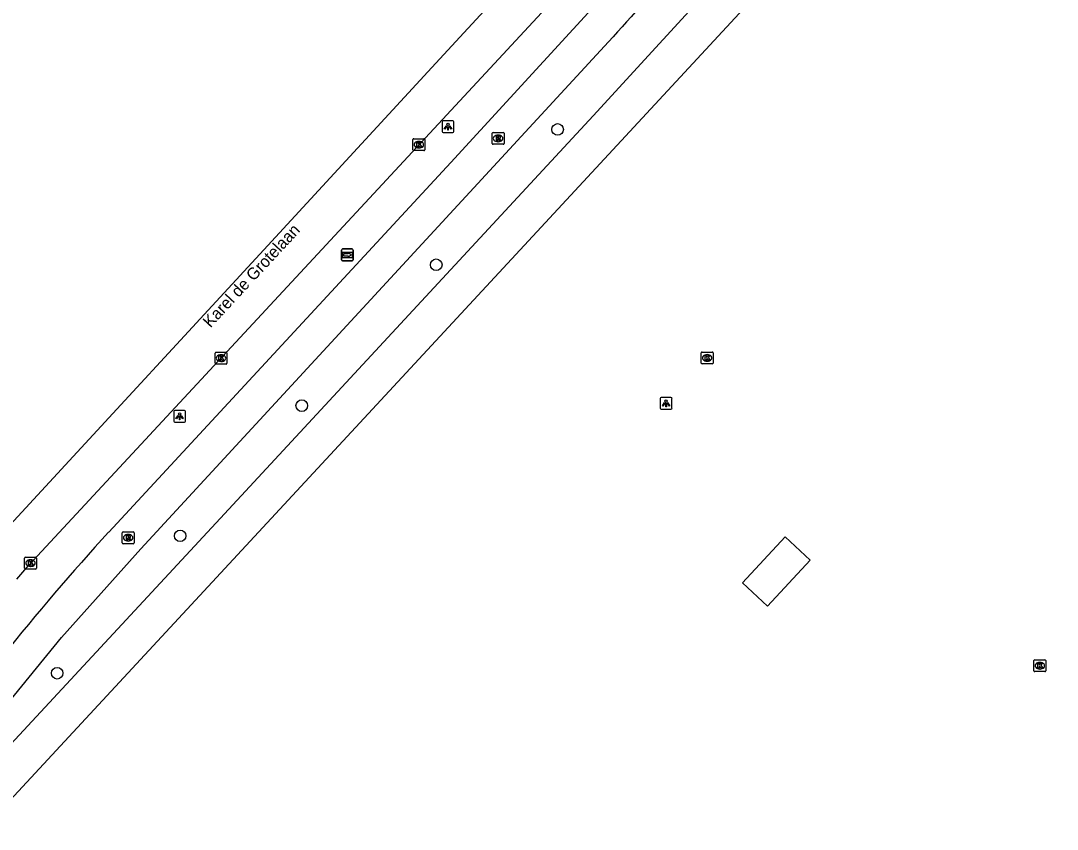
# Model space of a CAD drawing. Extents: x 159222 to 160346, y 381249 to 382166.
# Drawn here: x 159951.7 to 160039.1, y 381973.4 to 382041.6 of the extents above; entities that cross this region are included whole.
import ezdxf

# ---------------------------------------------------------------- set-up
doc = ezdxf.new("R2010")
doc.units = 0
for name, color, linetype in [('IMGEO_Boom', 7, 'Continuous'), ('IMGEO_Fietspad_gesloten', 7, 'Continuous'), ('IMGEO_Kolk', 7, 'Continuous'), ('IMGEO_Lichtpunt', 7, 'Continuous'), ('IMGEO_Openbare_ruimte_label', 7, 'Continuous'), ('IMGEO_Pand', 7, 'Continuous'), ('IMGEO_Rijbaan_regionaal_gesloten', 7, 'Continuous'), ('IMGEO_Rioolput', 7, 'Continuous'), ('IMGEO_Voetpad_open', 7, 'Continuous'), ('IMGEO_Wegwijzer', 7, 'Continuous')]:
    doc.layers.add(name, color=color, linetype=linetype)

msp = doc.modelspace()

# ---------------------------------------------------------------- linework, layer by layer
at = {"layer": 'IMGEO_Boom'}
for centre in [(159996.995, 382032.391), (159986.761, 382020.982), (159975.43, 382009.107), (159965.18, 381998.134), (159954.81, 381986.553)]:
    msp.add_circle(centre, 0.489, dxfattribs=at)
at = {"layer": 'IMGEO_Fietspad_gesloten'}
for points in [[(160000.807, 382043.591), (159987.982, 382029.591), (159959.152, 381998.446)], [(159942.998, 381974.993), (159946.971, 381979.545), (159955.163, 381989.569), (159961.853, 381997.042), (160001.291, 382039.769)]]:
    msp.add_lwpolyline(points, dxfattribs=at)
for centre, radius, start, end in [((160149.508, 381908.206), 198.185, 133.16173, 138.40657), ((160109.113, 381861.281), 203.231, 137.55179, 141.42825)]:
    msp.add_arc(centre, radius, start, end, dxfattribs=at)
at = {"layer": 'IMGEO_Kolk'}
for p, q in [((159984.799, 382030.681), (159984.799, 382031.533)), ((159984.874, 382031.607), (159985.726, 382031.607)), ((159985.8, 382031.533), (159985.8, 382030.681)), ((159985.726, 382030.607), (159984.874, 382030.607)), ((159985.31, 382030.827), (159985.285, 382030.827)), ((159985.287, 382031.387), (159985.312, 382031.387)), ((159968.121, 382012.687), (159968.121, 382013.539)), ((159968.196, 382013.613), (159969.048, 382013.613)), ((159968.609, 382013.393), (159968.634, 382013.393)), ((159969.122, 382013.539), (159969.122, 382012.687)), ((160009.098, 382012.702), (160009.098, 382013.554)), ((160009.173, 382013.628), (160010.025, 382013.628)), ((160009.586, 382013.408), (160009.611, 382013.408)), ((160010.099, 382013.554), (160010.099, 382012.702)), ((159969.048, 382012.613), (159968.196, 382012.613)), ((159968.632, 382012.833), (159968.607, 382012.833)), ((160010.025, 382012.628), (160009.173, 382012.628)), ((160009.609, 382012.848), (160009.584, 382012.848)), ((159952.063, 381995.408), (159952.063, 381996.26)), ((159952.138, 381996.334), (159952.99, 381996.334)), ((159952.551, 381996.114), (159952.576, 381996.114)), ((159953.064, 381996.26), (159953.064, 381995.408)), ((159952.99, 381995.334), (159952.138, 381995.334)), ((159952.574, 381995.554), (159952.549, 381995.554)), ((160037.144, 381986.762), (160037.144, 381987.614)), ((160037.219, 381987.688), (160038.071, 381987.688)), ((160037.655, 381986.908), (160037.63, 381986.908)), ((160037.632, 381987.468), (160037.657, 381987.468)), ((160038.145, 381987.614), (160038.145, 381986.762)), ((160038.071, 381986.688), (160037.219, 381986.688))]:
    msp.add_line(p, q, dxfattribs=at)
for points in [[(159984.799, 382030.681), (159984.799, 382031.533)], [(159984.874, 382031.607), (159985.726, 382031.607)], [(159985.8, 382031.533), (159985.8, 382030.681)], [(159985.726, 382030.607), (159984.874, 382030.607)], [(159985.12, 382031.307), (159985.243, 382031.307), (159985.243, 382031.156), (159985.373, 382031.307), (159985.537, 382031.307), (159985.391, 382031.156), (159985.544, 382030.907), (159985.392, 382030.907), (159985.307, 382031.071), (159985.243, 382031.004), (159985.243, 382030.907), (159985.12, 382030.907), (159985.12, 382031.307)], [(159968.121, 382012.687), (159968.121, 382013.539)], [(159968.196, 382013.613), (159969.048, 382013.613)], [(159968.442, 382013.313), (159968.565, 382013.313), (159968.565, 382013.162), (159968.695, 382013.313), (159968.859, 382013.313), (159968.713, 382013.162), (159968.866, 382012.913), (159968.714, 382012.913), (159968.629, 382013.077), (159968.565, 382013.01), (159968.565, 382012.913), (159968.442, 382012.913), (159968.442, 382013.313)], [(159969.122, 382013.539), (159969.122, 382012.687)], [(160009.098, 382012.702), (160009.098, 382013.554)], [(160009.173, 382013.628), (160010.025, 382013.628)], [(160009.419, 382013.328), (160009.542, 382013.328), (160009.542, 382013.177), (160009.672, 382013.328), (160009.836, 382013.328), (160009.69, 382013.177), (160009.843, 382012.928), (160009.691, 382012.928), (160009.606, 382013.092), (160009.542, 382013.025), (160009.542, 382012.928), (160009.419, 382012.928), (160009.419, 382013.328)], [(160010.099, 382013.554), (160010.099, 382012.702)], [(159969.048, 382012.613), (159968.196, 382012.613)], [(160010.025, 382012.628), (160009.173, 382012.628)], [(159952.063, 381995.408), (159952.063, 381996.26)], [(159952.138, 381996.334), (159952.99, 381996.334)], [(159952.384, 381996.034), (159952.507, 381996.034), (159952.507, 381995.883), (159952.637, 381996.034), (159952.801, 381996.034), (159952.655, 381995.883), (159952.808, 381995.634), (159952.656, 381995.634), (159952.571, 381995.798), (159952.507, 381995.731), (159952.507, 381995.634), (159952.384, 381995.634), (159952.384, 381996.034)], [(159953.064, 381996.26), (159953.064, 381995.408)], [(159952.99, 381995.334), (159952.138, 381995.334)], [(160037.144, 381986.762), (160037.144, 381987.614)], [(160037.219, 381987.688), (160038.071, 381987.688)], [(160037.465, 381987.388), (160037.588, 381987.388), (160037.588, 381987.237), (160037.718, 381987.388), (160037.882, 381987.388), (160037.736, 381987.237), (160037.889, 381986.988), (160037.737, 381986.988), (160037.652, 381987.152), (160037.588, 381987.085), (160037.588, 381986.988), (160037.465, 381986.988), (160037.465, 381987.388)], [(160038.145, 381987.614), (160038.145, 381986.762)], [(160038.071, 381986.688), (160037.219, 381986.688)]]:
    msp.add_lwpolyline(points, dxfattribs=at)
for centre, start, end in [((159984.876, 382031.531), 91.55205, 178.44795), ((159984.876, 382031.531), 91.55205, 178.44795), ((159985.724, 382031.531), 1.55205, 88.44795), ((159985.724, 382031.531), 1.55205, 88.44795), ((159984.876, 382030.683), 181.55205, 268.44795), ((159984.876, 382030.683), 181.55205, 268.44795), ((159985.724, 382030.683), 271.55205, 358.44795), ((159985.724, 382030.683), 271.55205, 358.44795), ((159968.198, 382013.537), 91.55205, 178.44795), ((159968.198, 382013.537), 91.55205, 178.44795), ((159969.046, 382013.537), 1.55205, 88.44795), ((159969.046, 382013.537), 1.55205, 88.44795), ((160009.175, 382013.552), 91.55205, 178.44795), ((160009.175, 382013.552), 91.55205, 178.44795), ((160010.023, 382013.552), 1.55205, 88.44795), ((160010.023, 382013.552), 1.55205, 88.44795), ((159968.198, 382012.689), 181.55205, 268.44795), ((159968.198, 382012.689), 181.55205, 268.44795), ((159969.046, 382012.689), 271.55205, 358.44795), ((159969.046, 382012.689), 271.55205, 358.44795), ((160009.175, 382012.704), 181.55205, 268.44795), ((160009.175, 382012.704), 181.55205, 268.44795), ((160010.023, 382012.704), 271.55205, 358.44795), ((160010.023, 382012.704), 271.55205, 358.44795), ((159952.14, 381996.258), 91.55205, 178.44795), ((159952.14, 381996.258), 91.55205, 178.44795), ((159952.988, 381996.258), 1.55205, 88.44795), ((159952.988, 381996.258), 1.55205, 88.44795), ((159952.14, 381995.41), 181.55205, 268.44795), ((159952.14, 381995.41), 181.55205, 268.44795), ((159952.988, 381995.41), 271.55205, 358.44795), ((159952.988, 381995.41), 271.55205, 358.44795), ((160037.221, 381987.612), 91.55205, 178.44795), ((160037.221, 381987.612), 91.55205, 178.44795), ((160038.069, 381987.612), 1.55205, 88.44795), ((160038.069, 381987.612), 1.55205, 88.44795), ((160037.221, 381986.764), 181.55205, 268.44795), ((160037.221, 381986.764), 181.55205, 268.44795), ((160038.069, 381986.764), 271.55205, 358.44795), ((160038.069, 381986.764), 271.55205, 358.44795)]:
    msp.add_arc(centre, 0.0765, start, end, dxfattribs=at)
for centre, major_axis, ratio, start_param, end_param in [((159985.286, 382031.107), (-0.387, 0.002), 0.722429, 4.712389, 7.853982), ((159985.311, 382031.107), (-0.39, 0.002), 0.717154, 1.570796, 4.712389), ((159968.608, 382013.113), (-0.387, 0.002), 0.722429, 4.712389, 7.853982), ((159968.633, 382013.113), (-0.39, 0.002), 0.717154, 1.570796, 4.712389), ((160009.585, 382013.128), (-0.387, 0.002), 0.722429, 4.712389, 7.853982), ((160009.61, 382013.128), (-0.39, 0.002), 0.717154, 1.570796, 4.712389), ((159952.55, 381995.834), (-0.387, 0.002), 0.722429, 4.712389, 7.853982), ((159952.575, 381995.834), (-0.39, 0.002), 0.717154, 1.570796, 4.712389), ((160037.631, 381987.188), (-0.387, 0.002), 0.722429, 4.712389, 7.853982), ((160037.656, 381987.188), (-0.39, 0.002), 0.717154, 1.570796, 4.712389)]:
    msp.add_ellipse(centre, major_axis=major_axis, ratio=ratio, start_param=start_param, end_param=end_param, dxfattribs=at)
at = {"layer": 'IMGEO_Lichtpunt'}
for p, q in [((159987.257, 382033.035), (159987.257, 382032.228)), ((159987.257, 382033.035), (159987.257, 382032.228)), ((159988.159, 382033.13), (159987.351, 382033.13)), ((159988.159, 382033.13), (159987.351, 382033.13)), ((159988.253, 382032.228), (159988.253, 382033.035)), ((159988.253, 382032.228), (159988.253, 382033.035)), ((159987.351, 382032.134), (159988.159, 382032.134)), ((159987.351, 382032.134), (159988.159, 382032.134)), ((160005.639, 382009.701), (160005.639, 382008.894)), ((160005.639, 382009.701), (160005.639, 382008.894)), ((160006.541, 382009.796), (160005.733, 382009.796)), ((160006.541, 382009.796), (160005.733, 382009.796)), ((160006.635, 382008.894), (160006.635, 382009.701)), ((160006.635, 382008.894), (160006.635, 382009.701)), ((159965.535, 382008.708), (159964.727, 382008.708)), ((159965.535, 382008.708), (159964.727, 382008.708)), ((160005.733, 382008.8), (160006.541, 382008.8)), ((160005.733, 382008.8), (160006.541, 382008.8)), ((159964.633, 382008.613), (159964.633, 382007.806)), ((159964.633, 382008.613), (159964.633, 382007.806)), ((159965.629, 382007.806), (159965.629, 382008.613)), ((159965.629, 382007.806), (159965.629, 382008.613)), ((159964.727, 382007.712), (159965.535, 382007.712)), ((159964.727, 382007.712), (159965.535, 382007.712))]:
    msp.add_line(p, q, dxfattribs=at)
for points in [[(159987.631, 382032.699), (159987.67, 382032.671), (159987.482, 382032.409), (159987.444, 382032.436), (159987.631, 382032.699)], [(159987.733, 382032.651), (159987.78, 382032.651), (159987.78, 382032.329), (159987.733, 382032.329), (159987.733, 382032.651)], [(159987.843, 382032.671), (159987.881, 382032.698), (159988.068, 382032.436), (159988.029, 382032.408), (159987.843, 382032.671)], [(160006.013, 382009.365), (160006.052, 382009.337), (160005.864, 382009.075), (160005.826, 382009.102), (160006.013, 382009.365)], [(160006.115, 382009.317), (160006.162, 382009.317), (160006.162, 382008.995), (160006.115, 382008.995), (160006.115, 382009.317)], [(160006.225, 382009.337), (160006.263, 382009.364), (160006.45, 382009.102), (160006.411, 382009.074), (160006.225, 382009.337)], [(159965.007, 382008.277), (159965.046, 382008.249), (159964.858, 382007.987), (159964.82, 382008.014), (159965.007, 382008.277)], [(159965.109, 382008.229), (159965.156, 382008.229), (159965.156, 382007.907), (159965.109, 382007.907), (159965.109, 382008.229)], [(159965.219, 382008.249), (159965.257, 382008.276), (159965.444, 382008.014), (159965.405, 382007.986), (159965.219, 382008.249)]]:
    msp.add_lwpolyline(points, dxfattribs=at)
for centre in [(159987.756, 382032.833), (160006.138, 382009.499), (159965.132, 382008.411)]:
    msp.add_circle(centre, 0.0994, dxfattribs=at)
for centre, start, end in [((159987.351, 382033.035), 90, 180), ((159987.351, 382033.035), 90, 180), ((159988.159, 382033.035), 0, 90), ((159988.159, 382033.035), 0, 90), ((159987.351, 382032.228), 180, 270), ((159987.351, 382032.228), 180, 270), ((159988.159, 382032.228), 270, 0), ((159988.159, 382032.228), 270, 360), ((160005.733, 382009.701), 90, 180), ((160005.733, 382009.701), 90, 180), ((160006.541, 382009.701), 0, 90), ((160006.541, 382009.701), 0, 90), ((159964.727, 382008.613), 90, 180), ((159964.727, 382008.613), 90, 180), ((159965.535, 382008.613), 0, 90), ((159965.535, 382008.613), 0, 90), ((160005.733, 382008.894), 180, 270), ((160005.733, 382008.894), 180, 270), ((160006.541, 382008.894), 270, 0), ((160006.541, 382008.894), 270, 360), ((159964.727, 382007.806), 180, 270), ((159964.727, 382007.806), 180, 270), ((159965.535, 382007.806), 270, 0), ((159965.535, 382007.806), 270, 360)]:
    msp.add_arc(centre, 0.0946, start, end, dxfattribs=at)
at = {"layer": 'IMGEO_Pand'}
msp.add_lwpolyline([(160012.569, 381994.185), (160016.18, 381998.053), (160018.29, 381996.083), (160014.679, 381992.215), (160012.569, 381994.185)], dxfattribs=at)
at = {"layer": 'IMGEO_Rijbaan_regionaal_gesloten'}
for points in [[(159874.745, 381914.947), (159885.463, 381927.149), (159896.686, 381939.831), (159901.476, 381945.231), (159912.72, 381957.722), (159926.438, 381972.6), (159953.155, 382001.55), (159972.237, 382022.246), (159986.384, 382037.608), (160022.311, 382076.536), (160036.596, 382092.047), (160042.055, 382097.856), (160047.812, 382103.453), (160050.825, 382106.009), (160053.948, 382108.432), (160060.685, 382112.66), (160064.272, 382114.5), (160066.702, 382115.586), (160071.312, 382117.395), (160073.297, 382118.105)], [(159951.416, 381994.471), (159952.421, 381995.674), (160007.622, 382055.183)]]:
    msp.add_lwpolyline(points, dxfattribs=at)
at = {"layer": 'IMGEO_Rioolput'}
for p, q in [((159991.474, 382031.212), (159991.474, 382032.064)), ((159991.549, 382032.138), (159992.401, 382032.138)), ((159991.962, 382031.918), (159991.987, 382031.918)), ((159992.475, 382032.064), (159992.475, 382031.212)), ((159992.401, 382031.138), (159991.549, 382031.138)), ((159991.985, 382031.358), (159991.96, 382031.358)), ((159960.296, 381997.544), (159960.296, 381998.396)), ((159960.371, 381998.47), (159961.223, 381998.47)), ((159960.784, 381998.25), (159960.809, 381998.25)), ((159961.297, 381998.396), (159961.297, 381997.544)), ((159961.223, 381997.47), (159960.371, 381997.47)), ((159960.807, 381997.69), (159960.782, 381997.69))]:
    msp.add_line(p, q, dxfattribs=at)
for points in [[(159991.474, 382031.212), (159991.474, 382032.064)], [(159991.549, 382032.138), (159992.401, 382032.138)], [(159992.063, 382031.836), (159991.811, 382031.838), (159991.811, 382031.438)], [(159991.811, 382031.438), (159991.935, 382031.438), (159991.935, 382031.6), (159991.946, 382031.6)], [(159991.989, 382031.757), (159991.935, 382031.757), (159991.935, 382031.676)], [(159991.935, 382031.676), (159991.987, 382031.676)], [(159991.993, 382031.571), (159992.064, 382031.438), (159992.204, 382031.438), (159992.139, 382031.564)], [(159992.475, 382032.064), (159992.475, 382031.212)], [(159992.401, 382031.138), (159991.549, 382031.138)], [(159960.296, 381997.544), (159960.296, 381998.396)], [(159960.371, 381998.47), (159961.223, 381998.47)], [(159961.297, 381998.396), (159961.297, 381997.544)], [(159961.223, 381997.47), (159960.371, 381997.47)], [(159960.885, 381998.168), (159960.633, 381998.17), (159960.633, 381997.77)], [(159960.633, 381997.77), (159960.757, 381997.77), (159960.757, 381997.932), (159960.768, 381997.932)], [(159960.811, 381998.089), (159960.757, 381998.089), (159960.757, 381998.008)], [(159960.757, 381998.008), (159960.809, 381998.008)], [(159960.815, 381997.903), (159960.886, 381997.77), (159961.026, 381997.77), (159960.961, 381997.896)]]:
    msp.add_lwpolyline(points, dxfattribs=at)
for centre, radius, start, end in [((159991.551, 382032.062), 0.0765, 91.55205, 178.44795), ((159991.551, 382032.062), 0.0765, 91.55205, 178.44795), ((159991.945, 382031.547), 0.0533, 26.02933, 88.69889), ((159991.971, 382031.865), 0.19, 274.7715, 282.96867), ((159991.995, 382031.661), 0.0964, 77.00612, 93.18647), ((159992.009, 382031.718), 0.0378, 276.66336, 79.67722), ((159992.062, 382031.726), 0.109, 350.36119, 89.41601), ((159992.06, 382031.726), 0.112, 277.58423, 350.98172), ((159992.044, 382031.511), 0.108, 29.51342, 73.79051), ((159992.399, 382032.062), 0.0765, 1.55205, 88.44795), ((159992.399, 382032.062), 0.0765, 1.55205, 88.44795), ((159991.551, 382031.214), 0.0765, 181.55205, 268.44795), ((159991.551, 382031.214), 0.0765, 181.55205, 268.44795), ((159992.399, 382031.214), 0.0765, 271.55205, 358.44795), ((159992.399, 382031.214), 0.0765, 271.55205, 358.44795), ((159960.373, 381998.394), 0.0765, 91.55205, 178.44795), ((159960.373, 381998.394), 0.0765, 91.55205, 178.44795), ((159961.221, 381998.394), 0.0765, 1.55205, 88.44795), ((159961.221, 381998.394), 0.0765, 1.55205, 88.44795), ((159960.373, 381997.546), 0.0765, 181.55205, 268.44795), ((159960.373, 381997.546), 0.0765, 181.55205, 268.44795), ((159960.767, 381997.879), 0.0533, 26.02933, 88.69889), ((159960.793, 381998.197), 0.19, 274.7715, 282.96867), ((159960.817, 381997.993), 0.0964, 77.00612, 93.18647), ((159960.831, 381998.05), 0.0378, 276.66336, 79.67722), ((159960.884, 381998.058), 0.109, 350.36119, 89.41601), ((159960.882, 381998.058), 0.112, 277.58423, 350.98172), ((159960.866, 381997.843), 0.108, 29.51342, 73.79051), ((159961.221, 381997.546), 0.0765, 271.55205, 358.44795), ((159961.221, 381997.546), 0.0765, 271.55205, 358.44795)]:
    msp.add_arc(centre, radius, start, end, dxfattribs=at)
for centre, major_axis, ratio, start_param, end_param in [((159991.961, 382031.638), (-0.387, 0.002), 0.722429, 4.712389, 7.853982), ((159991.986, 382031.638), (-0.39, 0.002), 0.717154, 1.570796, 4.712389), ((159960.783, 381997.97), (-0.387, 0.002), 0.722429, 4.712389, 7.853982), ((159960.808, 381997.97), (-0.39, 0.002), 0.717154, 1.570796, 4.712389)]:
    msp.add_ellipse(centre, major_axis=major_axis, ratio=ratio, start_param=start_param, end_param=end_param, dxfattribs=at)
at = {"layer": 'IMGEO_Voetpad_open'}
for points in [[(160063.301, 382097.262), (160055.435, 382088.686), (160053.206, 382086.345), (160037.081, 382068.942), (160033.976, 382065.592), (159923.424, 381946.282), (159883.094, 381902.756)], [(159944.486, 381973.614), (159944.596, 381973.734), (159950.178, 381979.784), (159968.911, 382000), (160000, 382033.55), (160029.172, 382065.404), (160029.254, 382065.51), (160035.386, 382072.084), (160034.951, 382072.504)]]:
    msp.add_lwpolyline(points, dxfattribs=at)
at = {"layer": 'IMGEO_Wegwijzer'}
for p, q in [((159978.774, 382021.413), (159978.774, 382022.213)), ((159978.774, 382022.213), (159978.774, 382021.413)), ((159978.874, 382022.313), (159979.664, 382022.313)), ((159979.664, 382022.313), (159978.874, 382022.313)), ((159979.764, 382022.213), (159979.764, 382021.413)), ((159979.764, 382021.413), (159979.764, 382022.213)), ((159979.664, 382021.313), (159978.874, 382021.313)), ((159978.874, 382021.313), (159979.664, 382021.313))]:
    msp.add_line(p, q, dxfattribs=at)
for points in [[(159978.875, 382022.045), (159979.663, 382022.045), (159979.663, 382021.581), (159978.875, 382021.581), (159978.875, 382022.045)], [(159978.94, 382021.897), (159978.94, 382021.813), (159978.94, 382021.729), (159979.351, 382021.729), (159979.351, 382021.646), (159979.598, 382021.813), (159979.351, 382021.98), (159979.351, 382021.897), (159978.94, 382021.897)]]:
    msp.add_lwpolyline(points, dxfattribs=at)
for centre, start, end in [((159978.874, 382022.213), 90, 180), ((159978.874, 382022.213), 90, 180), ((159979.664, 382022.213), 0, 90), ((159979.664, 382022.213), 360, 90), ((159978.874, 382021.413), 180, 270), ((159978.874, 382021.413), 180, 270), ((159979.664, 382021.413), 270, 0), ((159979.664, 382021.413), 270, 0)]:
    msp.add_arc(centre, 0.1, start, end, dxfattribs=at)

# ---------------------------------------------------------------- texts
at = {"layer": 'IMGEO_Openbare_ruimte_label'}
msp.add_text('Karel de Grotelaan', height=1, rotation=47.14809, dxfattribs=at).set_placement((159967.725, 382015.616))

doc.saveas('drawing.dxf')
